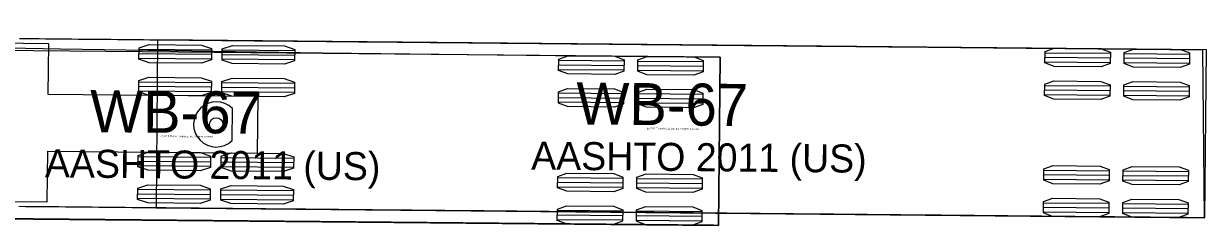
# Model space of a CAD drawing. Extents: x 2175591 to 2194071, y 76570 to 86955.
# Drawn here: x 2193142 to 2193201.8, y 86758.3 to 86768.5 of the extents above; entities that cross this region are included whole.
import ezdxf

# ---------------------------------------------------------------- set-up
doc = ezdxf.new("R2010")
doc.units = 0
doc.layers.add('-NOPLT', color=7, linetype='Continuous')
doc.layers.add('C-UTIL-STRM-TEXT', color=7, linetype='Continuous')

msp = doc.modelspace()

# ---------------------------------------------------------------- linework, layer by layer
at = {"layer": '-NOPLT'}
for p, q in [((2193143.251, 86767.489), (2193128.252, 86767.631)), ((2193143.227, 86764.922), (2193143.251, 86767.489)), ((2193147.815, 86767.216), (2193151.482, 86767.181)), ((2193148.753, 86767.687), (2193148.673, 86759.187)), ((2193201.751, 86767.184), (2193148.753, 86767.687)), ((2193152.015, 86767.176), (2193155.682, 86767.142)), ((2193201.67, 86758.684), (2193201.751, 86767.184)), ((2193147.811, 86766.758), (2193151.477, 86766.723)), ((2193147.813, 86766.987), (2193151.48, 86766.952)), ((2193152.011, 86766.718), (2193155.677, 86766.683)), ((2193152.013, 86766.947), (2193155.679, 86766.912)), ((2193193.595, 86766.574), (2193196.894, 86766.543)), ((2193193.597, 86766.803), (2193196.897, 86766.772)), ((2193193.599, 86767.032), (2193196.899, 86767.001)), ((2193197.594, 86766.536), (2193200.894, 86766.505)), ((2193197.597, 86766.765), (2193200.896, 86766.734)), ((2193197.599, 86766.994), (2193200.899, 86766.963)), ((2193147.797, 86765.337), (2193151.464, 86765.302)), ((2193147.8, 86765.566), (2193151.466, 86765.532)), ((2193151.999, 86765.526), (2193155.666, 86765.492)), ((2193193.583, 86765.382), (2193196.883, 86765.351)), ((2193197.583, 86765.344), (2193200.883, 86765.313)), ((2193153.826, 86764.822), (2193143.227, 86764.922)), ((2193147.795, 86765.108), (2193151.462, 86765.073)), ((2193151.995, 86765.068), (2193155.662, 86765.033)), ((2193151.997, 86765.297), (2193155.664, 86765.263)), ((2193153.799, 86761.955), (2193153.826, 86764.822)), ((2193193.579, 86764.924), (2193196.879, 86764.893)), ((2193193.581, 86765.153), (2193196.881, 86765.122)), ((2193197.579, 86764.886), (2193200.879, 86764.855)), ((2193197.581, 86765.115), (2193200.881, 86765.084)), ((2193152.513, 86762.593), (2193152.528, 86764.209)), ((2193143.175, 86759.489), (2193143.199, 86762.056)), ((2193143.199, 86762.056), (2193153.799, 86761.955)), ((2193147.764, 86761.783), (2193151.43, 86761.748)), ((2193151.964, 86761.743), (2193155.63, 86761.709)), ((2193147.759, 86761.325), (2193151.426, 86761.29)), ((2193147.762, 86761.554), (2193151.428, 86761.519)), ((2193151.959, 86761.285), (2193155.626, 86761.25)), ((2193151.961, 86761.514), (2193155.628, 86761.479)), ((2193193.538, 86760.641), (2193196.838, 86760.61)), ((2193193.54, 86760.87), (2193196.84, 86760.839)), ((2193193.543, 86761.099), (2193196.843, 86761.068)), ((2193197.538, 86760.603), (2193200.838, 86760.572)), ((2193197.54, 86760.832), (2193200.84, 86760.801)), ((2193197.542, 86761.061), (2193200.842, 86761.03)), ((2193147.748, 86760.133), (2193151.415, 86760.098)), ((2193151.948, 86760.093), (2193155.614, 86760.059)), ((2193176.851, 86758.306), (2193039.055, 86759.613)), ((2193128.176, 86759.631), (2193143.175, 86759.489)), ((2193147.744, 86759.675), (2193151.41, 86759.64)), ((2193147.746, 86759.904), (2193151.412, 86759.869)), ((2193151.944, 86759.635), (2193155.61, 86759.6)), ((2193151.946, 86759.864), (2193155.612, 86759.829)), ((2193193.527, 86759.449), (2193196.827, 86759.418)), ((2193197.527, 86759.411), (2193200.827, 86759.38)), ((2193148.673, 86759.187), (2193201.67, 86758.684)), ((2193148.673, 86759.187), (2193148.673, 86759.187)), ((2193193.523, 86758.991), (2193196.823, 86758.96)), ((2193193.525, 86759.22), (2193196.825, 86759.189)), ((2193197.522, 86758.953), (2193200.822, 86758.922)), ((2193197.525, 86759.182), (2193200.825, 86759.151))]:
    msp.add_line(p, q, dxfattribs=at)
for points in [[(2193141.773, 86767.753), (2193142.103, 86767.75), (2193142.432, 86767.746), (2193142.762, 86767.743), (2193143.092, 86767.74), (2193143.421, 86767.737), (2193143.751, 86767.734), (2193144.08, 86767.731), (2193144.41, 86767.728), (2193144.74, 86767.725), (2193145.069, 86767.721), (2193145.399, 86767.718), (2193145.729, 86767.715), (2193146.058, 86767.712), (2193146.388, 86767.709), (2193146.718, 86767.706), (2193147.047, 86767.703), (2193147.377, 86767.7), (2193147.706, 86767.696), (2193148.036, 86767.693), (2193148.366, 86767.69), (2193148.695, 86767.687), (2193149.025, 86767.684), (2193149.355, 86767.681), (2193149.684, 86767.678), (2193150.014, 86767.675), (2193150.344, 86767.671), (2193150.673, 86767.668), (2193151.003, 86767.665), (2193151.332, 86767.662), (2193151.662, 86767.659), (2193151.992, 86767.656), (2193152.321, 86767.653), (2193152.651, 86767.65), (2193152.981, 86767.646), (2193153.31, 86767.643), (2193153.64, 86767.64), (2193153.969, 86767.637), (2193154.299, 86767.634), (2193154.629, 86767.631), (2193154.958, 86767.628), (2193155.288, 86767.625), (2193155.618, 86767.621), (2193155.947, 86767.618), (2193156.277, 86767.615), (2193156.606, 86767.612), (2193156.936, 86767.609), (2193157.265, 86767.606), (2193157.595, 86767.603), (2193157.924, 86767.6), (2193158.253, 86767.596), (2193158.582, 86767.593), (2193158.912, 86767.59), (2193159.24, 86767.587), (2193159.569, 86767.584), (2193159.898, 86767.581), (2193160.226, 86767.578), (2193160.555, 86767.575), (2193160.883, 86767.572), (2193161.211, 86767.568), (2193161.538, 86767.565), (2193161.865, 86767.562), (2193162.192, 86767.559), (2193162.519, 86767.556), (2193162.846, 86767.553), (2193163.172, 86767.55), (2193163.498, 86767.547), (2193163.823, 86767.544), (2193164.148, 86767.541), (2193164.473, 86767.537), (2193164.798, 86767.534), (2193165.122, 86767.531), (2193165.446, 86767.528), (2193165.77, 86767.525), (2193166.094, 86767.522), (2193166.417, 86767.519), (2193166.74, 86767.516), (2193167.063, 86767.513), (2193167.386, 86767.51), (2193167.709, 86767.507), (2193168.031, 86767.504), (2193168.354, 86767.501), (2193168.676, 86767.498), (2193168.998, 86767.495), (2193169.321, 86767.492), (2193169.643, 86767.488), (2193169.965, 86767.485), (2193170.288, 86767.482), (2193170.61, 86767.479), (2193170.933, 86767.476), (2193171.255, 86767.473), (2193171.578, 86767.47), (2193171.901, 86767.467), (2193172.224, 86767.464), (2193172.547, 86767.461), (2193172.871, 86767.458), (2193173.194, 86767.455), (2193173.518, 86767.452), (2193173.842, 86767.449), (2193174.167, 86767.446), (2193174.491, 86767.443), (2193174.816, 86767.439), (2193175.141, 86767.436), (2193175.467, 86767.433), (2193175.793, 86767.43), (2193176.119, 86767.427), (2193176.445, 86767.424), (2193176.772, 86767.421), (2193177.099, 86767.418), (2193177.427, 86767.415), (2193177.755, 86767.412), (2193178.083, 86767.408), (2193178.411, 86767.405), (2193178.74, 86767.402), (2193179.069, 86767.399), (2193179.399, 86767.396), (2193179.728, 86767.393), (2193180.058, 86767.39), (2193180.388, 86767.387), (2193180.719, 86767.383), (2193181.049, 86767.38), (2193181.38, 86767.377), (2193181.711, 86767.374), (2193182.042, 86767.371), (2193182.373, 86767.368), (2193182.704, 86767.365), (2193183.035, 86767.361), (2193183.367, 86767.358), (2193183.698, 86767.355), (2193184.03, 86767.352), (2193184.361, 86767.349), (2193184.692, 86767.346), (2193185.024, 86767.343), (2193185.355, 86767.34), (2193185.687, 86767.336), (2193186.018, 86767.333), (2193186.35, 86767.33), (2193186.681, 86767.327), (2193187.013, 86767.324), (2193187.344, 86767.321), (2193187.675, 86767.318), (2193188.006, 86767.314), (2193188.338, 86767.311), (2193188.669, 86767.308), (2193189, 86767.305), (2193189.331, 86767.302), (2193189.662, 86767.299), (2193189.993, 86767.296), (2193190.324, 86767.292), (2193190.655, 86767.289), (2193190.986, 86767.286), (2193191.317, 86767.283), (2193191.648, 86767.28), (2193191.979, 86767.277), (2193192.309, 86767.274), (2193192.64, 86767.27), (2193192.971, 86767.267), (2193193.302, 86767.264), (2193193.632, 86767.261), (2193193.963, 86767.258), (2193194.293, 86767.255), (2193194.624, 86767.252), (2193194.954, 86767.248), (2193195.285, 86767.245), (2193195.615, 86767.242), (2193195.945, 86767.239), (2193196.276, 86767.236), (2193196.386, 86767.235), (2193196.496, 86767.234), (2193196.606, 86767.233), (2193196.716, 86767.232), (2193196.826, 86767.231), (2193196.936, 86767.23), (2193197.046, 86767.229), (2193197.156, 86767.228), (2193197.266, 86767.227), (2193197.377, 86767.226), (2193197.487, 86767.224), (2193197.597, 86767.223), (2193197.707, 86767.222), (2193197.817, 86767.221), (2193197.927, 86767.22), (2193198.037, 86767.219), (2193198.147, 86767.218), (2193198.257, 86767.217), (2193198.367, 86767.216), (2193198.477, 86767.215), (2193198.587, 86767.214), (2193198.697, 86767.213), (2193198.807, 86767.212), (2193198.917, 86767.211), (2193199.027, 86767.21), (2193199.137, 86767.209), (2193199.247, 86767.208), (2193199.357, 86767.207), (2193199.467, 86767.206), (2193199.577, 86767.205), (2193199.687, 86767.204), (2193199.797, 86767.203), (2193199.907, 86767.202), (2193200.017, 86767.201), (2193200.127, 86767.199), (2193200.237, 86767.198), (2193200.347, 86767.197), (2193200.457, 86767.196), (2193200.566, 86767.195), (2193200.676, 86767.194), (2193200.786, 86767.193), (2193200.896, 86767.192), (2193201.006, 86767.191), (2193201.116, 86767.19), (2193201.226, 86767.189), (2193201.336, 86767.188), (2193201.446, 86767.187), (2193201.556, 86767.186), (2193201.642, 86758.685)], [(2193201.642, 86758.685), (2193201.597, 86758.685), (2193201.552, 86758.686), (2193201.507, 86758.686), (2193201.463, 86758.686), (2193201.42, 86758.687), (2193201.376, 86758.687), (2193201.334, 86758.688), (2193201.178, 86758.689), (2193201.066, 86758.69), (2193200.954, 86758.691), (2193200.841, 86758.692), (2193200.729, 86758.693), (2193200.617, 86758.694), (2193200.504, 86758.695), (2193200.392, 86758.697), (2193200.279, 86758.698), (2193200.167, 86758.699), (2193200.055, 86758.7), (2193199.942, 86758.701), (2193199.83, 86758.702), (2193199.717, 86758.703), (2193199.605, 86758.704), (2193199.493, 86758.705), (2193199.38, 86758.706), (2193199.268, 86758.707), (2193199.155, 86758.708), (2193199.043, 86758.709), (2193198.931, 86758.71), (2193198.818, 86758.711), (2193198.706, 86758.713), (2193198.593, 86758.714), (2193198.481, 86758.715), (2193198.368, 86758.716), (2193198.256, 86758.717), (2193198.143, 86758.718), (2193198.031, 86758.719), (2193197.918, 86758.72), (2193197.806, 86758.721), (2193197.693, 86758.722), (2193197.581, 86758.723), (2193197.468, 86758.724), (2193197.356, 86758.725), (2193197.243, 86758.726), (2193197.131, 86758.727), (2193197.018, 86758.729), (2193196.906, 86758.73), (2193196.793, 86758.731), (2193196.681, 86758.732), (2193196.568, 86758.733), (2193196.456, 86758.734), (2193196.343, 86758.735), (2193196.231, 86758.736), (2193196.118, 86758.737), (2193196.006, 86758.738), (2193195.893, 86758.739), (2193195.78, 86758.74), (2193195.443, 86758.743), (2193195.105, 86758.747), (2193194.767, 86758.75), (2193194.429, 86758.753), (2193194.092, 86758.756), (2193193.754, 86758.759), (2193193.416, 86758.763), (2193193.078, 86758.766), (2193192.74, 86758.769), (2193192.402, 86758.772), (2193192.064, 86758.776), (2193191.726, 86758.779), (2193191.387, 86758.782), (2193191.049, 86758.785), (2193190.711, 86758.788), (2193190.373, 86758.792), (2193190.034, 86758.795), (2193189.696, 86758.798), (2193189.358, 86758.801), (2193189.019, 86758.804), (2193188.681, 86758.808), (2193188.342, 86758.811), (2193188.004, 86758.814), (2193187.665, 86758.817), (2193187.326, 86758.82), (2193186.988, 86758.824), (2193186.649, 86758.827), (2193186.31, 86758.83), (2193185.971, 86758.833), (2193185.633, 86758.836), (2193185.294, 86758.84), (2193184.955, 86758.843), (2193184.616, 86758.846), (2193184.277, 86758.849), (2193183.938, 86758.853), (2193183.599, 86758.856), (2193183.261, 86758.859), (2193182.922, 86758.862), (2193182.583, 86758.865), (2193182.244, 86758.869), (2193181.905, 86758.872), (2193181.567, 86758.875), (2193181.228, 86758.878), (2193180.89, 86758.881), (2193180.552, 86758.885), (2193180.214, 86758.888), (2193179.876, 86758.891), (2193179.538, 86758.894), (2193179.2, 86758.897), (2193178.863, 86758.901), (2193178.526, 86758.904), (2193178.189, 86758.907), (2193177.853, 86758.91), (2193177.517, 86758.913), (2193177.181, 86758.917), (2193176.845, 86758.92), (2193176.51, 86758.923), (2193176.175, 86758.926), (2193175.841, 86758.929), (2193175.507, 86758.932), (2193175.173, 86758.936), (2193174.84, 86758.939), (2193174.507, 86758.942), (2193174.174, 86758.945), (2193173.841, 86758.948), (2193173.509, 86758.951), (2193173.177, 86758.955), (2193172.846, 86758.958), (2193172.514, 86758.961), (2193172.183, 86758.964), (2193171.852, 86758.967), (2193171.522, 86758.97), (2193171.191, 86758.973), (2193170.861, 86758.977), (2193170.531, 86758.98), (2193170.201, 86758.983), (2193169.871, 86758.986), (2193169.541, 86758.989), (2193169.212, 86758.992), (2193168.882, 86758.995), (2193168.553, 86758.998), (2193168.223, 86759.002), (2193167.894, 86759.005), (2193167.564, 86759.008), (2193167.234, 86759.011), (2193166.905, 86759.014), (2193166.575, 86759.017), (2193166.245, 86759.02), (2193165.915, 86759.023), (2193165.585, 86759.027), (2193165.254, 86759.03), (2193164.924, 86759.033), (2193164.593, 86759.036), (2193164.262, 86759.039), (2193163.931, 86759.042), (2193163.599, 86759.045), (2193163.267, 86759.049), (2193162.935, 86759.052), (2193162.602, 86759.055), (2193162.27, 86759.058), (2193161.937, 86759.061), (2193161.603, 86759.064), (2193161.269, 86759.067), (2193160.935, 86759.071), (2193160.601, 86759.074), (2193160.266, 86759.077), (2193159.932, 86759.08), (2193159.596, 86759.083), (2193159.261, 86759.087), (2193158.925, 86759.09), (2193158.59, 86759.093), (2193158.254, 86759.096), (2193157.917, 86759.099), (2193157.581, 86759.102), (2193157.245, 86759.106), (2193156.908, 86759.109), (2193156.572, 86759.112), (2193156.235, 86759.115), (2193155.898, 86759.118), (2193155.561, 86759.122), (2193155.224, 86759.125), (2193154.888, 86759.128), (2193154.551, 86759.131), (2193154.214, 86759.134), (2193153.877, 86759.138), (2193153.54, 86759.141), (2193153.203, 86759.144), (2193152.866, 86759.147), (2193152.529, 86759.15), (2193152.192, 86759.154), (2193151.855, 86759.157), (2193151.518, 86759.16), (2193151.181, 86759.163), (2193150.844, 86759.166), (2193150.507, 86759.17), (2193150.17, 86759.173), (2193149.833, 86759.176), (2193149.496, 86759.179), (2193149.159, 86759.182), (2193148.822, 86759.185), (2193148.485, 86759.189), (2193148.148, 86759.192), (2193147.811, 86759.195), (2193147.474, 86759.198), (2193147.137, 86759.201), (2193146.8, 86759.205), (2193146.463, 86759.208), (2193146.126, 86759.211), (2193145.789, 86759.214), (2193145.452, 86759.217), (2193145.115, 86759.221), (2193144.778, 86759.224), (2193144.441, 86759.227), (2193144.104, 86759.23), (2193143.767, 86759.233), (2193143.43, 86759.237), (2193143.093, 86759.24), (2193142.756, 86759.243), (2193142.419, 86759.246), (2193142.082, 86759.249), (2193141.745, 86759.253)]]:
    msp.add_lwpolyline(points, dxfattribs=at)
for points in [[(2193147.81, 86766.701), (2193147.816, 86767.273), (2193148.331, 86767.441), (2193150.971, 86767.415), (2193151.482, 86767.238), (2193151.477, 86766.666), (2193150.962, 86766.499), (2193148.322, 86766.524)], [(2193152.01, 86766.661), (2193152.016, 86767.233), (2193152.531, 86767.401), (2193155.17, 86767.376), (2193155.682, 86767.198), (2193155.677, 86766.627), (2193155.162, 86766.459), (2193152.522, 86766.484)], [(2193193.594, 86766.517), (2193193.599, 86767.089), (2193194.063, 86767.257), (2193196.439, 86767.234), (2193196.899, 86767.058), (2193196.894, 86766.486), (2193196.43, 86766.318), (2193194.054, 86766.34)], [(2193197.594, 86766.479), (2193197.599, 86767.051), (2193198.063, 86767.219), (2193200.439, 86767.196), (2193200.899, 86767.02), (2193200.894, 86766.448), (2193200.43, 86766.28), (2193198.054, 86766.302)], [(2193147.795, 86765.051), (2193147.8, 86765.623), (2193148.315, 86765.791), (2193150.955, 86765.766), (2193151.467, 86765.588), (2193151.461, 86765.016), (2193150.946, 86764.849), (2193148.306, 86764.874)], [(2193151.995, 86765.011), (2193152, 86765.583), (2193152.515, 86765.751), (2193155.155, 86765.726), (2193155.666, 86765.549), (2193155.661, 86764.977), (2193155.146, 86764.809), (2193152.506, 86764.834)], [(2193193.578, 86764.867), (2193193.584, 86765.439), (2193194.047, 86765.607), (2193196.423, 86765.584), (2193196.884, 86765.408), (2193196.878, 86764.836), (2193196.415, 86764.668), (2193194.039, 86764.69)], [(2193197.578, 86764.829), (2193197.584, 86765.401), (2193198.047, 86765.569), (2193200.423, 86765.547), (2193200.883, 86765.37), (2193200.878, 86764.798), (2193200.414, 86764.63), (2193198.039, 86764.652)], [(2193147.759, 86761.268), (2193147.764, 86761.84), (2193148.279, 86762.007), (2193150.919, 86761.982), (2193151.431, 86761.805), (2193151.425, 86761.233), (2193150.91, 86761.066), (2193148.271, 86761.091)], [(2193151.959, 86761.228), (2193151.964, 86761.8), (2193152.479, 86761.968), (2193155.119, 86761.943), (2193155.631, 86761.765), (2193155.625, 86761.193), (2193155.11, 86761.026), (2193152.47, 86761.051)], [(2193193.538, 86760.584), (2193193.543, 86761.156), (2193194.007, 86761.324), (2193196.383, 86761.301), (2193196.843, 86761.125), (2193196.838, 86760.553), (2193196.374, 86760.385), (2193193.998, 86760.407)], [(2193197.538, 86760.546), (2193197.543, 86761.118), (2193198.007, 86761.286), (2193200.383, 86761.263), (2193200.843, 86761.087), (2193200.837, 86760.515), (2193200.374, 86760.347), (2193197.998, 86760.369)], [(2193147.743, 86759.618), (2193147.749, 86760.19), (2193148.264, 86760.358), (2193150.903, 86760.332), (2193151.415, 86760.155), (2193151.41, 86759.583), (2193150.895, 86759.416), (2193148.255, 86759.441)], [(2193151.943, 86759.578), (2193151.948, 86760.15), (2193152.463, 86760.318), (2193155.103, 86760.293), (2193155.615, 86760.115), (2193155.61, 86759.543), (2193155.095, 86759.376), (2193152.455, 86759.401)], [(2193193.522, 86758.934), (2193193.528, 86759.506), (2193193.991, 86759.674), (2193196.367, 86759.651), (2193196.827, 86759.475), (2193196.822, 86758.903), (2193196.358, 86758.735), (2193193.982, 86758.757)], [(2193197.522, 86758.896), (2193197.527, 86759.468), (2193197.991, 86759.636), (2193200.367, 86759.614), (2193200.827, 86759.437), (2193200.822, 86758.865), (2193200.358, 86758.697), (2193197.982, 86758.719)]]:
    msp.add_lwpolyline(points, close=True, dxfattribs=at)
msp.add_circle((2193151.713, 86763.408), 0.34, dxfattribs=at)
msp.add_arc((2193151.713, 86763.408), 1.143, 44.4568, 314.4568, dxfattribs=at)
at = {"layer": 'C-UTIL-STRM-TEXT'}
for p, q in [((2193177.175, 86766.804), (2193124.178, 86767.291)), ((2193169.024, 86766.65), (2193172.323, 86766.619)), ((2193173.023, 86766.613), (2193176.323, 86766.583)), ((2193177.097, 86758.304), (2193177.175, 86766.804)), ((2193169.019, 86766.191), (2193172.319, 86766.161)), ((2193169.022, 86766.42), (2193172.321, 86766.39)), ((2193173.019, 86766.155), (2193176.319, 86766.124)), ((2193173.021, 86766.384), (2193176.321, 86766.353)), ((2193169.006, 86764.77), (2193172.306, 86764.74)), ((2193169.008, 86765), (2193172.308, 86764.969)), ((2193173.006, 86764.734), (2193176.306, 86764.703)), ((2193173.008, 86764.963), (2193176.308, 86764.933)), ((2193169.004, 86764.541), (2193172.304, 86764.511)), ((2193173.004, 86764.505), (2193176.304, 86764.474)), ((2193168.969, 86760.716), (2193172.269, 86760.686)), ((2193172.969, 86760.68), (2193176.269, 86760.649)), ((2193168.965, 86760.258), (2193172.265, 86760.228)), ((2193168.967, 86760.487), (2193172.267, 86760.457)), ((2193172.965, 86760.221), (2193176.265, 86760.191)), ((2193172.967, 86760.451), (2193176.267, 86760.42)), ((2193124.1, 86758.791), (2193177.097, 86758.304)), ((2193168.952, 86758.837), (2193172.252, 86758.807)), ((2193168.954, 86759.067), (2193172.254, 86759.036)), ((2193172.952, 86758.801), (2193176.252, 86758.77)), ((2193172.954, 86759.03), (2193176.254, 86759)), ((2193168.95, 86758.608), (2193172.25, 86758.578)), ((2193172.95, 86758.572), (2193176.249, 86758.541))]:
    msp.add_line(p, q, dxfattribs=at)
for points in [[(2193090.902, 86768.502), (2193104.138, 86768.122), (2193117.375, 86767.783), (2193130.612, 86767.486), (2193143.85, 86767.233), (2193157.087, 86767.026), (2193170.327, 86766.868), (2193177.175, 86766.804), (2193177.097, 86758.304), (2193176.851, 86758.306), (2193176.851, 86758.306)], [(2193176.851, 86758.306), (2193124.1, 86758.791), (2193110.943, 86759.128), (2193097.681, 86759.503), (2193084.42, 86759.914)]]:
    msp.add_lwpolyline(points, dxfattribs=at)
for points in [[(2193169.019, 86766.134), (2193169.024, 86766.706), (2193169.488, 86766.874), (2193171.864, 86766.853), (2193172.324, 86766.676), (2193172.319, 86766.104), (2193171.855, 86765.936), (2193169.479, 86765.958)], [(2193173.019, 86766.098), (2193173.024, 86766.67), (2193173.488, 86766.838), (2193175.863, 86766.816), (2193176.324, 86766.639), (2193176.319, 86766.067), (2193175.855, 86765.899), (2193173.479, 86765.921)], [(2193169.004, 86764.484), (2193169.009, 86765.056), (2193169.473, 86765.225), (2193171.848, 86765.203), (2193172.309, 86765.026), (2193172.304, 86764.454), (2193171.84, 86764.286), (2193169.464, 86764.308)], [(2193173.004, 86764.448), (2193173.009, 86765.02), (2193173.472, 86765.188), (2193175.848, 86765.166), (2193176.309, 86764.989), (2193176.303, 86764.417), (2193175.84, 86764.249), (2193173.464, 86764.271)], [(2193168.964, 86760.201), (2193168.97, 86760.773), (2193169.433, 86760.941), (2193171.809, 86760.92), (2193172.27, 86760.743), (2193172.264, 86760.171), (2193171.801, 86760.003), (2193169.425, 86760.025)], [(2193172.964, 86760.165), (2193172.969, 86760.737), (2193173.433, 86760.905), (2193175.809, 86760.883), (2193176.269, 86760.706), (2193176.264, 86760.134), (2193175.801, 86759.966), (2193173.425, 86759.988)], [(2193168.949, 86758.551), (2193168.955, 86759.123), (2193169.418, 86759.291), (2193171.794, 86759.27), (2193172.254, 86759.093), (2193172.249, 86758.521), (2193171.786, 86758.353), (2193169.41, 86758.375)], [(2193172.949, 86758.515), (2193172.954, 86759.087), (2193173.418, 86759.255), (2193175.794, 86759.233), (2193176.254, 86759.056), (2193176.249, 86758.484), (2193175.785, 86758.316), (2193173.409, 86758.338)]]:
    msp.add_lwpolyline(points, close=True, dxfattribs=at)

# ---------------------------------------------------------------- texts
at = {"layer": '-NOPLT'}
for s, height, p in [('WB-67', 2.125, (2193169.901, 86763.406)), ('(c) 2022 Transoft Solutions, Inc. All rights reserved.', 0.085, (2193173.471, 86763.159)), ('AASHTO 2011 (US)', 1.41667, (2193167.628, 86761.125))]:
    msp.add_text(s, height=height, rotation=359.4568, dxfattribs=at).set_placement(p)
at = {"layer": 'C-UTIL-STRM-TEXT'}
for s, height, p in [('WB-67', 2.125, (2193145.327, 86763.016)), ('(c) 2019 Transoft Solutions, Inc. All rights reserved.', 0.085, (2193148.905, 86762.771)), ('AASHTO 2011 (US)', 1.41667, (2193143.054, 86760.735))]:
    msp.add_text(s, height=height, rotation=359.4739, dxfattribs=at).set_placement(p)

doc.saveas('drawing.dxf')
